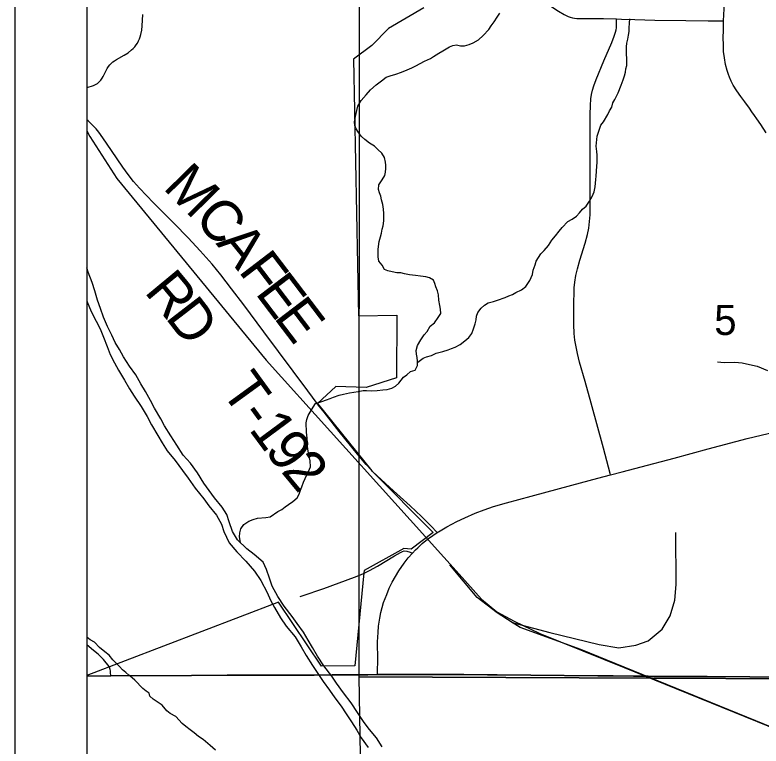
# Model space of a CAD drawing. Extents: x 0 to 34, y 0 to 22.
# Drawn here: x 17.758 to 18.796, y 13.524 to 14.541 of the extents above; entities that cross this region are included whole.
import ezdxf

# ---------------------------------------------------------------- set-up
doc = ezdxf.new("R2010")
doc.units = 0
for name, color, linetype in [('GM_X_City_Street', 7, 'Continuous'), ('GM_X_Corporation', 7, 'Continuous'), ('GM_X_County_Road', 7, 'Continuous'), ('GM_X_Major_River', 7, 'Continuous'), ('GM_X_Minor_River', 7, 'Continuous'), ('GM_X_Rail_Line', 7, 'Continuous'), ('GM_X_Section', 7, 'Continuous'), ('GM_X_Section_Text', 7, 'Continuous'), ('GM_X_State_Route', 7, 'Continuous'), ('GM_X_Township_Road', 7, 'Continuous'), ('GM_X_Township_Road_Text', 7, 'Continuous'), ('SH_Data', 7, 'Continuous')]:
    doc.layers.add(name, color=color, linetype=linetype)

msp = doc.modelspace()

# ---------------------------------------------------------------- linework, layer by layer
at = {"layer": 'GM_X_City_Street'}
for points in [[(18.5866, 13.9016), (18.5861, 13.9037), (18.5766, 13.9387), (18.5594, 14.0016), (18.5511, 14.0315), (18.5435, 14.0584), (18.5404, 14.0705), (18.5386, 14.0797), (18.5371, 14.0889), (18.5362, 14.0983), (18.5357, 14.1107), (18.5357, 14.1403), (18.536, 14.1561), (18.5362, 14.1616), (18.537, 14.1698), (18.5383, 14.179), (18.5404, 14.1882), (18.5438, 14.2002), (18.5512, 14.2239), (18.5544, 14.2358), (18.5563, 14.2449), (18.5575, 14.254), (18.5582, 14.2633), (18.5584, 14.2756), (18.5581, 14.3067), (18.5584, 14.3439), (18.5583, 14.3718), (18.5582, 14.4028), (18.5585, 14.4152), (18.5592, 14.4246), (18.5602, 14.4308), (18.5615, 14.4369), (18.5633, 14.4429), (18.5665, 14.4517), (18.5774, 14.4775), (18.5884, 14.5032), (18.5918, 14.5118), (18.5937, 14.5176), (18.5943, 14.5206), (18.5947, 14.5236), (18.5949, 14.527), (18.5949, 14.534), (18.5949, 14.5358)], [(18.2437, 13.7651), (18.2513, 13.7687), (18.2622, 13.7746), (18.2862, 13.7891), (18.2943, 13.7936), (18.2972, 13.7952), (18.2995, 13.7958), (18.3032, 13.7955), (18.3076, 13.794), (18.3111, 13.7928)]]:
    msp.add_lwpolyline(points, dxfattribs=at)
at = {"layer": 'GM_X_Corporation'}
msp.add_lwpolyline([(18.3267, 14.5511), (18.2775, 14.5227), (18.2545, 14.4989), (18.229, 14.4797), (18.236, 14.1228), (18.2892, 14.1237), (18.2889, 14.0367), (18.2468, 14.0231), (18.2043, 14.0246), (18.1787, 14.0009), (18.2547, 13.9074), (18.3397, 13.8213), (18.3092, 13.7984), (18.2992, 13.7993), (18.2439, 13.7686), (18.2435, 13.7656), (18.2308, 13.636), (18.1845, 13.6357), (18.1244, 13.7245), (17.8579, 13.6228), (17.8579, 13.6223), (18.2307, 13.6242), (18.2621, 13.6244), (18.5688, 13.6227), (18.9182, 13.6203)], dxfattribs=at)
at = {"layer": 'GM_X_County_Road'}
msp.add_line((17.8579, 13.6218), (17.8913, 13.6222), dxfattribs=at)
for points in [[(18.7439, 14.5331), (18.7448, 14.5498), (18.7486, 14.5965), (18.7522, 14.6351)], [(18.7436, 14.5176), (18.7437, 14.5253), (18.7439, 14.5331)], [(18.8029, 14.3776), (18.7956, 14.3889), (18.7901, 14.3967), (18.7867, 14.4016), (18.7833, 14.4064), (18.7798, 14.4115), (18.7733, 14.4206), (18.768, 14.4279), (18.7625, 14.4358), (18.7574, 14.4438), (18.7545, 14.4492), (18.7519, 14.4548), (18.7506, 14.4583), (18.7488, 14.4641), (18.7467, 14.4723), (18.745, 14.4815), (18.7439, 14.4907), (18.7436, 14.4969), (18.7434, 14.5125), (18.7436, 14.5176)], [(17.8913, 13.6222), (18.0034, 13.6226), (18.0531, 13.623), (18.1463, 13.6233), (18.1744, 13.6233)], [(18.1744, 13.6233), (18.1994, 13.6234), (18.2254, 13.6236), (18.2309, 13.6236), (18.233, 13.6236)], [(18.233, 13.6236), (18.2487, 13.6237), (18.2623, 13.6238)], [(18.2623, 13.6238), (18.3825, 13.6238), (18.569, 13.6222), (18.5902, 13.622)], [(18.5902, 13.622), (18.6467, 13.6214), (18.7092, 13.6212)], [(18.7092, 13.6212), (18.7211, 13.6212), (18.7802, 13.6207), (18.8671, 13.6201), (18.9075, 13.6198), (18.9184, 13.6198)]]:
    msp.add_lwpolyline(points, dxfattribs=at)
at = {"layer": 'GM_X_Major_River'}
for points in [[(17.9091, 14.0658), (17.9034, 14.076), (17.8972, 14.0858), (17.8926, 14.096), (17.8865, 14.1078), (17.8811, 14.121), (17.8768, 14.1331), (17.873, 14.1448), (17.8691, 14.1577), (17.8652, 14.169), (17.8598, 14.1838), (17.8579, 14.1894)], [(17.8579, 14.144), (17.8586, 14.1421), (17.864, 14.1288), (17.8709, 14.1156), (17.8763, 14.1046), (17.8813, 14.0933), (17.8863, 14.0801), (17.8905, 14.0691), (17.8963, 14.0574), (17.902, 14.0472), (17.9105, 14.0332), (17.9174, 14.0215), (17.9239, 14.011), (17.9334, 13.9966), (17.9419, 13.9827), (17.948, 13.9713), (17.9568, 13.9566), (17.9629, 13.9464), (17.9695, 13.9351), (17.9809, 13.9215), (17.9909, 13.9079), (17.9989, 13.897), (18.0088, 13.883), (18.0207, 13.8683), (18.0276, 13.8585), (18.0383, 13.8457), (18.0452, 13.8329), (18.0486, 13.823), (18.0559, 13.8072), (18.0666, 13.7944), (18.0792, 13.7816), (18.0911, 13.7676), (18.0999, 13.7548), (18.1087, 13.7382), (18.1137, 13.7276), (18.119, 13.7174), (18.1275, 13.7027), (18.1355, 13.691), (18.1477, 13.6763), (18.1562, 13.6627), (18.1631, 13.6506), (18.1719, 13.6366), (18.1795, 13.6253), (18.1868, 13.6144), (18.1956, 13.6023), (18.2029, 13.5917), (18.2116, 13.58), (18.2189, 13.5691), (18.2262, 13.5582), (18.2335, 13.5468), (18.2396, 13.5359), (18.2495, 13.5223)], [(18.2688, 13.5236), (18.2608, 13.5357), (18.2513, 13.5474), (18.2436, 13.5572), (18.2344, 13.5711), (18.2256, 13.5847), (18.2149, 13.5983), (18.2054, 13.6119), (18.1989, 13.6217), (18.1878, 13.636), (18.179, 13.6496), (18.1717, 13.6617), (18.1659, 13.6719), (18.1594, 13.6828), (18.1506, 13.6949), (18.1438, 13.7047), (18.1327, 13.719), (18.1239, 13.7326), (18.1158, 13.7469), (18.112, 13.7579), (18.1081, 13.77), (18.1031, 13.7802), (18.0909, 13.7911), (18.0806, 13.799), (18.0677, 13.8114), (18.0604, 13.8231), (18.0561, 13.8364), (18.0526, 13.8466), (18.0461, 13.8568), (18.0354, 13.8696), (18.0209, 13.89), (18.0121, 13.9047), (18.0022, 13.9179), (17.9922, 13.9292), (17.9834, 13.9428), (17.975, 13.956), (17.9662, 13.9699), (17.9608, 13.9798), (17.952, 13.9945), (17.9466, 14.0051), (17.9397, 14.0175), (17.9332, 14.0285), (17.9263, 14.0406), (17.9171, 14.053), (17.9091, 14.0658)]]:
    msp.add_lwpolyline(points, dxfattribs=at)
at = {"layer": 'GM_X_Minor_River'}
for points in [[(18.2711, 14.2551), (18.271, 14.2654), (18.2705, 14.2714), (18.2697, 14.2775), (18.2681, 14.2843), (18.2669, 14.2892), (18.2653, 14.2938), (18.2637, 14.2987), (18.264, 14.3052), (18.2688, 14.3121), (18.2726, 14.3178), (18.2737, 14.3228), (18.274, 14.3277), (18.2739, 14.3323), (18.2735, 14.3368), (18.2719, 14.3429), (18.2684, 14.3493), (18.263, 14.3541), (18.2584, 14.3586), (18.2511, 14.3631), (18.2449, 14.3683), (18.2399, 14.3724), (18.2357, 14.3777), (18.2326, 14.383), (18.2306, 14.3875), (18.2305, 14.3928), (18.2316, 14.4001), (18.2337, 14.4085), (18.2352, 14.4145), (18.2397, 14.4222), (18.2464, 14.4303), (18.2528, 14.4372), (18.2603, 14.4441), (18.2678, 14.4499), (18.2742, 14.455), (18.2799, 14.4565), (18.2879, 14.4589), (18.2958, 14.4617), (18.3034, 14.4648), (18.3102, 14.468), (18.3159, 14.4707), (18.3279, 14.4769), (18.3359, 14.4808), (18.3404, 14.4836), (18.3476, 14.4882), (18.3532, 14.4913), (18.3581, 14.4944), (18.3627, 14.4968), (18.3672, 14.4987), (18.3721, 14.4996), (18.3779, 14.4985), (18.3836, 14.4982), (18.39, 14.5002), (18.3953, 14.5025), (18.4029, 14.5068), (18.4096, 14.5126), (18.4171, 14.5211), (18.4205, 14.526), (18.4246, 14.5318), (18.4287, 14.5383), (18.4324, 14.544)], [(18.3181, 14.0586), (18.3185, 14.0586), (18.3261, 14.064), (18.3306, 14.0656), (18.3374, 14.0676), (18.3442, 14.0707), (18.3533, 14.0731), (18.3605, 14.0755), (18.3651, 14.0775), (18.3704, 14.0791), (18.3775, 14.0829), (18.3839, 14.088), (18.3896, 14.0926), (18.3937, 14.0984), (18.3959, 14.1048), (18.3981, 14.1117), (18.3995, 14.1174), (18.4002, 14.1224), (18.4021, 14.1273), (18.4066, 14.1335), (18.4111, 14.1377), (18.4163, 14.1408), (18.4239, 14.1428), (18.4292, 14.1448), (18.4398, 14.1483), (18.4451, 14.1507), (18.4504, 14.1527), (18.455, 14.1554), (18.4629, 14.1589), (18.4685, 14.1635), (18.4741, 14.172), (18.4778, 14.1804), (18.4789, 14.1865), (18.4815, 14.1937), (18.4833, 14.1987), (18.4896, 14.209), (18.4941, 14.2136), (18.5001, 14.2206), (18.505, 14.2282), (18.5098, 14.234), (18.5151, 14.2405), (18.5192, 14.2459), (18.5271, 14.254), (18.5331, 14.2571), (18.5392, 14.2613), (18.5433, 14.2663), (18.5478, 14.271), (18.5527, 14.2752), (18.5571, 14.2821), (18.5609, 14.2886), (18.5638, 14.2951), (18.5652, 14.3023), (18.5663, 14.3126), (18.5666, 14.3172), (18.5672, 14.324), (18.5675, 14.3312), (18.5682, 14.3362), (18.5681, 14.3461), (18.5677, 14.3514), (18.5668, 14.359), (18.5671, 14.3635), (18.5678, 14.3726), (18.5703, 14.3799), (18.5729, 14.3879), (18.5766, 14.3925), (18.583, 14.4029), (18.5852, 14.4082), (18.5885, 14.4132), (18.59, 14.4189), (18.5926, 14.4235), (18.597, 14.433), (18.6014, 14.4437), (18.604, 14.451), (18.6058, 14.4567), (18.6073, 14.4617), (18.608, 14.4662), (18.6091, 14.4708), (18.6094, 14.4765), (18.6093, 14.4811), (18.6089, 14.4864), (18.6087, 14.497), (18.6091, 14.502), (18.6105, 14.5077), (18.6116, 14.513), (18.6123, 14.5183), (18.6126, 14.5233), (18.6129, 14.5301), (18.6132, 14.5358)], [(18.0716, 13.8077), (18.0703, 13.8156), (18.071, 13.8209), (18.0724, 13.8267), (18.0765, 13.8324), (18.0833, 13.8371), (18.0894, 13.8398), (18.0954, 13.8414), (18.1068, 13.8423), (18.1129, 13.8435), (18.1235, 13.8505), (18.1291, 13.8536), (18.134, 13.8571), (18.1385, 13.8606), (18.1446, 13.8645), (18.1506, 13.8699), (18.1532, 13.8748), (18.1554, 13.8802), (18.1569, 13.8851), (18.1594, 13.8913), (18.1617, 13.8966), (18.1639, 13.9016), (18.1665, 13.9062), (18.169, 13.9127), (18.1686, 13.921), (18.1673, 13.9274), (18.1661, 13.9346), (18.1649, 13.9411), (18.1644, 13.9472), (18.1643, 13.9525), (18.1635, 13.9612), (18.1633, 13.9741), (18.164, 13.9787), (18.1658, 13.9844), (18.1699, 13.9913), (18.1729, 13.9959), (18.1759, 14.0009), (18.185, 14.0036), (18.1914, 14.006), (18.1967, 14.008), (18.2013, 14.0099), (18.2088, 14.0123), (18.2149, 14.0139), (18.2232, 14.0156), (18.2293, 14.0168), (18.2354, 14.0176), (18.2426, 14.0189), (18.2472, 14.0189), (18.254, 14.0186), (18.262, 14.0191), (18.2696, 14.02), (18.2757, 14.0204), (18.2821, 14.0224), (18.2874, 14.0251), (18.2919, 14.029), (18.2983, 14.0374), (18.3032, 14.0409), (18.3081, 14.0452), (18.3149, 14.0475), (18.3182, 14.054), (18.3181, 14.0597), (18.3177, 14.0651), (18.3165, 14.0696), (18.316, 14.0745), (18.3179, 14.0814), (18.3227, 14.0894), (18.3275, 14.0963), (18.3313, 14.1009), (18.3358, 14.1086), (18.3418, 14.1132), (18.3466, 14.1205), (18.3504, 14.1259), (18.3499, 14.132), (18.3491, 14.1373), (18.3478, 14.1448), (18.347, 14.152), (18.3458, 14.1574), (18.3434, 14.163), (18.3422, 14.1676), (18.3403, 14.1725), (18.3345, 14.1758), (18.3295, 14.1773), (18.3223, 14.1779), (18.3151, 14.179), (18.3067, 14.18), (18.2998, 14.1814), (18.2949, 14.1825), (18.2892, 14.1828), (18.2827, 14.1842), (18.2766, 14.1853), (18.272, 14.1875), (18.2689, 14.1932), (18.2642, 14.1988), (18.2634, 14.2049), (18.2632, 14.2155), (18.2646, 14.2262), (18.2664, 14.2326), (18.2679, 14.2376), (18.269, 14.2433), (18.2701, 14.2479), (18.2711, 14.2551)], [(18.7352, 14.0588), (18.7446, 14.0581), (18.7594, 14.0586), (18.7696, 14.0575), (18.7799, 14.0553), (18.7905, 14.0528), (18.8049, 14.0468)], [(17.9249, 13.6162), (17.9211, 13.6195), (17.9165, 13.6229), (17.9122, 13.6266), (17.9076, 13.6307), (17.9034, 13.6352), (17.8995, 13.639), (17.8941, 13.6446), (17.8891, 13.651), (17.883, 13.6555), (17.8757, 13.6615), (17.8687, 13.669), (17.8626, 13.6723), (17.8579, 13.6758)], [(18.0369, 13.5189), (18.0295, 13.5252), (18.0196, 13.5335), (18.0134, 13.5379), (18.0073, 13.5428), (18.0015, 13.5469), (17.9957, 13.5518), (17.9904, 13.5559), (17.9819, 13.5656), (17.9738, 13.5697), (17.9692, 13.5734), (17.9626, 13.5813), (17.9504, 13.5895), (17.9457, 13.594), (17.9446, 13.5982), (17.9407, 13.6008), (17.9357, 13.6045), (17.9322, 13.6083), (17.9284, 13.6124), (17.9249, 13.6162)]]:
    msp.add_lwpolyline(points, dxfattribs=at)
at = {"layer": 'GM_X_Rail_Line'}
for points in [[(17.8579, 14.3802), (17.8619, 14.3724), (17.8997, 14.314), (18.1076, 14.061), (18.3759, 13.7634), (18.4069, 13.7287), (18.4286, 13.711), (18.4527, 13.6982), (18.4881, 13.6812), (18.6056, 13.6338), (18.6776, 13.6045), (18.8546, 13.5328)], [(18.4495, 13.6964), (18.5023, 13.6826), (18.5707, 13.6655), (18.5983, 13.6609), (18.622, 13.6649), (18.6391, 13.6708), (18.6582, 13.6872), (18.6694, 13.7056), (18.6759, 13.7273), (18.6779, 13.749), (18.6772, 13.8214)], [(18.4495, 13.6964), (18.4287, 13.7096), (18.401, 13.7313), (18.3629, 13.7767)], [(19.1192, 13.4268), (18.8239, 13.5452), (18.5451, 13.6589), (18.4609, 13.6892), (18.4495, 13.6964)]]:
    msp.add_lwpolyline(points, dxfattribs=at)
at = {"layer": 'GM_X_Section'}
for points in [[(18.2616, 14.6436), (19.26, 14.6381), (19.2565, 13.6162), (18.2369, 13.6209), (18.2374, 14.6442)], [(19.2565, 13.6162), (19.256, 12.6012), (18.2539, 12.6075), (18.2369, 13.6209)]]:
    msp.add_lwpolyline(points, close=True, dxfattribs=at)
at = {"layer": 'GM_X_State_Route'}
for points in [[(17.8736, 13.6521), (17.8674, 13.6575), (17.8579, 13.6651)], [(17.8913, 13.6222), (17.8911, 13.627), (17.8909, 13.629), (17.8905, 13.6311), (17.8893, 13.6341), (17.8875, 13.6369), (17.885, 13.6404), (17.8811, 13.6451), (17.8767, 13.6494), (17.8736, 13.6521)], [(18.1744, 13.6233), (18.1463, 13.6233), (18.0531, 13.623), (18.0034, 13.6226), (17.8913, 13.6222)], [(18.233, 13.6236), (18.2309, 13.6236), (18.2254, 13.6236), (18.1994, 13.6234), (18.1744, 13.6233)], [(18.2623, 13.6238), (18.2487, 13.6237), (18.233, 13.6236)], [(18.5902, 13.622), (18.569, 13.6222), (18.3825, 13.6238), (18.2623, 13.6238)], [(18.7092, 13.6212), (18.6467, 13.6214), (18.5902, 13.622)], [(18.9184, 13.6198), (18.9075, 13.6198), (18.8671, 13.6201), (18.7802, 13.6207), (18.7211, 13.6212), (18.7092, 13.6212)]]:
    msp.add_lwpolyline(points, dxfattribs=at)
at = {"layer": 'GM_X_Township_Road'}
for points in [[(18.4145, 14.6397), (18.4161, 14.638), (18.4193, 14.6346), (18.4362, 14.6164), (18.4488, 14.6027), (18.4619, 14.5896), (18.4705, 14.5803), (18.4764, 14.5741), (18.4814, 14.5694), (18.4889, 14.5635), (18.4965, 14.5583), (18.5142, 14.5468), (18.5221, 14.5421), (18.5276, 14.5394), (18.5305, 14.5383), (18.5335, 14.5374), (18.5365, 14.5368), (18.5396, 14.5365), (18.5427, 14.5363), (18.5551, 14.5363), (18.5768, 14.5363), (18.5949, 14.5358)], [(17.8579, 14.44), (17.8583, 14.4402), (17.8672, 14.4432), (17.8701, 14.4445), (17.8728, 14.4462), (17.8753, 14.4483), (17.8774, 14.4506), (17.8792, 14.4532), (17.8808, 14.4559), (17.8836, 14.4615), (17.8864, 14.4669), (17.8881, 14.4694), (17.8899, 14.4718), (17.8919, 14.4739), (17.8942, 14.4759), (17.8966, 14.4777), (17.8992, 14.4794), (17.9099, 14.4855), (17.9153, 14.4887), (17.9203, 14.4926), (17.9225, 14.4948), (17.9247, 14.4971), (17.9266, 14.4997), (17.9283, 14.5023), (17.9298, 14.5051), (17.9311, 14.508), (17.9322, 14.511), (17.9331, 14.514), (17.9343, 14.5202), (17.9351, 14.5264), (17.936, 14.5419)], [(18.5949, 14.5358), (18.6016, 14.5356), (18.6203, 14.535), (18.6482, 14.5342), (18.6913, 14.5336), (18.7226, 14.5332), (18.7349, 14.5333), (18.7422, 14.5331), (18.7439, 14.5331)], [(18.179, 14.0002), (18.1784, 14.001), (18.1655, 14.0185), (18.1452, 14.0461), (18.1042, 14.1008), (18.0762, 14.1381), (18.0594, 14.1605), (18.0442, 14.1801), (18.0323, 14.1945), (18.0158, 14.2131), (17.9988, 14.2312), (17.9793, 14.2513), (17.9508, 14.28), (17.9314, 14.3002), (17.9231, 14.3095), (17.9153, 14.3192), (17.908, 14.3294), (17.8924, 14.3527), (17.8802, 14.3706), (17.8747, 14.3781), (17.8708, 14.3829), (17.8666, 14.3873), (17.8649, 14.3891), (17.8624, 14.3915), (17.8598, 14.3939), (17.8581, 14.3954), (17.8579, 14.3955)], [(18.2538, 13.908), (18.2465, 13.916), (18.2345, 13.9303), (18.2091, 13.9618), (18.188, 13.9887), (18.179, 14.0002)], [(18.5866, 13.9016), (18.6026, 13.9058), (18.6294, 13.9129), (18.6753, 13.9251), (18.7225, 13.938), (18.7765, 13.9521), (18.8157, 13.9613), (18.8339, 13.9654), (18.8764, 13.9738), (18.9069, 13.9797), (18.9154, 13.9812)], [(18.3454, 13.8213), (18.3431, 13.8238), (18.3391, 13.8283), (18.3236, 13.8436), (18.3078, 13.8585), (18.2847, 13.8794), (18.2617, 13.9003), (18.255, 13.9068), (18.2538, 13.908)], [(18.3454, 13.8213), (18.3474, 13.8226), (18.3586, 13.8292), (18.3726, 13.8367), (18.3838, 13.842), (18.3983, 13.8483), (18.4106, 13.8532), (18.4236, 13.8577), (18.4417, 13.8629), (18.4761, 13.8722), (18.5325, 13.8873), (18.5689, 13.8969), (18.5866, 13.9016)], [(18.3111, 13.7928), (18.3152, 13.7972), (18.3186, 13.8004), (18.3247, 13.8061), (18.332, 13.812), (18.3395, 13.8175), (18.3454, 13.8213)], [(18.2623, 13.6238), (18.2623, 13.6278), (18.2627, 13.6443), (18.2625, 13.6693), (18.2631, 13.6825), (18.2639, 13.6913), (18.2656, 13.7025), (18.2671, 13.7103), (18.2709, 13.724), (18.2752, 13.7355), (18.2788, 13.7441), (18.2828, 13.7524), (18.2873, 13.7605), (18.2921, 13.7684), (18.2994, 13.7788), (18.3051, 13.7862), (18.3111, 13.7928)], [(18.1547, 13.7323), (18.1577, 13.7333), (18.1875, 13.7438), (18.2305, 13.7595), (18.2385, 13.7627), (18.2437, 13.7651)]]:
    msp.add_lwpolyline(points, dxfattribs=at)
at = {"layer": 'SH_Data'}
for p, q in [((17.7579, 16.0775), (17.7579, 9.0775)), ((17.8579, 15.9775), (17.8579, 9.1775))]:
    msp.add_line(p, q, dxfattribs=at)

# ---------------------------------------------------------------- texts
at = {"layer": 'GM_X_Section_Text'}
msp.add_text('5', height=0.0419, rotation=0, dxfattribs=at).set_placement((18.7308, 14.0962))
at = {"layer": 'GM_X_Township_Road_Text'}
for s, rotation, p in [('M', 314.4424, (17.9626, 14.3005)), ('C', 313.0858, (18.0055, 14.2567)), ('A', 309.1064, (18.0367, 14.2234)), ('F', 307.3693, (18.0679, 14.185)), ('R', 309.6479, (17.9368, 14.1561)), ('E', 307.2779, (18.0912, 14.1545)), ('D', 307.6076, (17.9662, 14.1205)), ('E', 307.2766, (18.1169, 14.1207)), ('T', 305.9639, (18.0434, 14.0187)), ('-', 306.068, (18.0684, 13.9842)), ('1', 306.495, (18.0824, 13.965)), ('9', 308.0277, (18.1042, 13.9355)), ('2', 309.7399, (18.127, 13.9065))]:
    msp.add_text(s, height=0.0568, rotation=rotation, dxfattribs=at).set_placement(p)

doc.saveas('drawing.dxf')
